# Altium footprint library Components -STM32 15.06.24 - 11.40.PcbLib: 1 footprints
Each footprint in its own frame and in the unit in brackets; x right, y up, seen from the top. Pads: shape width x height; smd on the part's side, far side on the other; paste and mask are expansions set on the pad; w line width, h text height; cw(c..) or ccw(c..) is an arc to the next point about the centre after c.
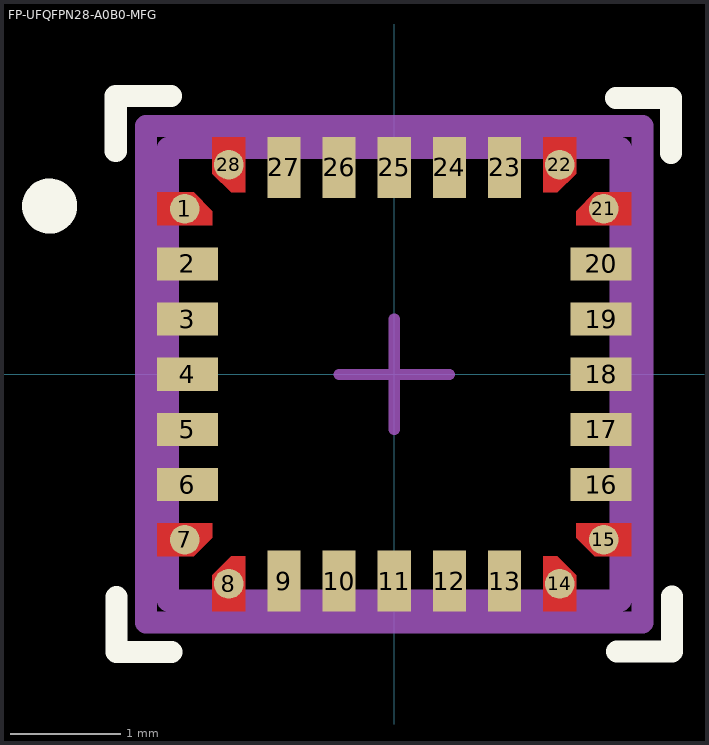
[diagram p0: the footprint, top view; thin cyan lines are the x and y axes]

## FP-UFQFPN28-A0B0-MFG [mm]
pads (28):
  round 0.27 smd paste+0 mask+0: 1(-1.9,1.5) 7(-1.9,-1.5) 8(-1.5,-1.9) 14(1.5,-1.9) 15(1.9,-1.5) 21(1.9,1.5) 22(1.5,1.9) 28(-1.5,1.9)
  rect 0.55x0.3 smd paste+0 mask+0: 2(-1.875,1) 3(-1.875,0.5) 4(-1.875,0) 5(-1.875,-0.5) 6(-1.875,-1) 16(1.875,-1) 17(1.875,-0.5) 18(1.875,0) 19(1.875,0.5) 20(1.875,1)
  rect 0.3x0.55 smd paste+0 mask+0: 9(-1,-1.875) 10(-0.5,-1.875) 11(0,-1.875) 12(0.5,-1.875) 13(1,-1.875) 23(1,1.875) 24(0.5,1.875) 25(0,1.875) 26(-0.5,1.875) 27(-1,1.875)
Top Layer:
  region: -1.35,1.65 -1.48,1.65 -1.65,1.82 -1.65,2.15 -1.35,2.15
  region: 1.35,1.65 1.48,1.65 1.65,1.82 1.65,2.15 1.35,2.15
  region: 1.35,-1.65 1.48,-1.65 1.65,-1.82 1.65,-2.15 1.35,-2.15
  region: -1.35,-1.65 -1.48,-1.65 -1.65,-1.82 -1.65,-2.15 -1.35,-2.15
  region: -1.65,1.35 -1.65,1.48 -1.82,1.65 -2.15,1.65 -2.15,1.35
  region: 1.65,1.35 1.65,1.48 1.82,1.65 2.15,1.65 2.15,1.35
  region: 1.65,-1.35 1.65,-1.48 1.82,-1.65 2.15,-1.65 2.15,-1.35
  region: -1.65,-1.35 -1.65,-1.48 -1.82,-1.65 -2.15,-1.65 -2.15,-1.35
Top Overlay:
  circle w0.25: c-3.125,1.525 r0.125
  lines w0.2: -2.525,2.025 -2.525,2.525 -2.025,2.525 ; -2.52,-2.02 -2.52,-2.52 -2.02,-2.52 ; 2.01,2.505 2.51,2.505 2.51,2.005 ; 2.02,-2.515 2.52,-2.515 2.52,-2.015
Top Assembly:
  lines w0.2: -2.25,-2.25 -2.25,2.25 2.25,2.25 2.25,-2.25 -2.25,-2.25
  text ".Designator" at 0,0.188 h1
Top 3D Body:
  lines w0.2: -2.05,-2.05 -2.05,2.05 2.05,2.05 2.05,-2.05 -2.05,-2.05
Top Courtyard:
  lines w0.2: -2.25,-2.25 -2.25,2.25 2.25,2.25 2.25,-2.25 -2.25,-2.25
Top Component Center:
  lines w0.1: -0.5,0 0.5,0 ; 0,-0.5 0,0.5
3D body "IC_STMicroelectronics_STM32L031G6U7_eec.STEP": height 0.25, standoff 0, extent -2.25,-2.25 2.25,2.25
